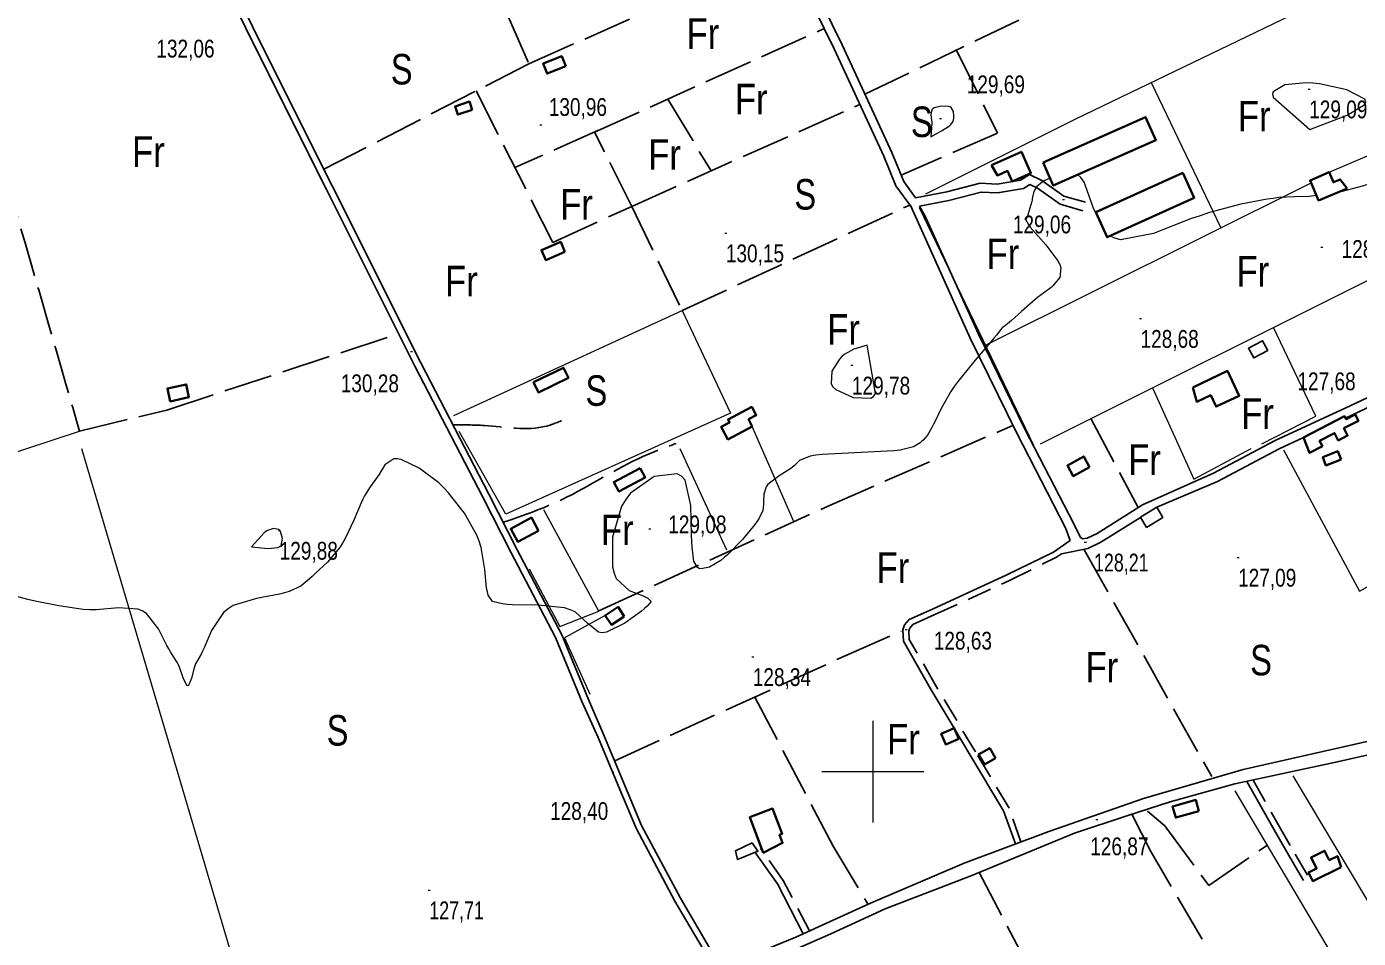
# Model space of a CAD drawing. Extents: x 483855 to 488461, y 4388206 to 4391419.
# Drawn here: x 485084 to 485739, y 4389918 to 4390366 of the extents above; entities that cross this region are included whole.
import ezdxf
from ezdxf.enums import TextEntityAlignment as Align

# ---------------------------------------------------------------- set-up
doc = ezdxf.new("R2010")
doc.units = 0
doc.header["$LTSCALE"] = 4
doc.linetypes.add('LONG_DASHED', pattern=[7.5, 6, -1.5])
doc.linetypes.add('MEDIUM_DASHED', pattern=[4.5, 3, -1.5])
for name, color, linetype, lineweight in [('1', 7, 'Continuous', 13), ('21', 7, 'Continuous', 25), ('25', 7, 'LONG_DASHED', 25), ('36', 7, 'Continuous', 25), ('38', 7, 'Continuous', 25), ('47', 7, 'Continuous', 35), ('48', 7, 'MEDIUM_DASHED', 25), ('51', 7, 'Continuous', 13), ('7', 7, 'Continuous', 13), ('9', 7, 'Continuous', 13)]:
    doc.layers.add(name, color=color, linetype=linetype, lineweight=lineweight)
doc.layers.add('31', color=7, linetype='Continuous')

msp = doc.modelspace()

# ---------------------------------------------------------------- linework, layer by layer
at = {"layer": '1'}
for p, q in [((485500, 4390025), (485500, 4389975)), ((485475, 4390000), (485525, 4390000))]:
    msp.add_line(p, q, dxfattribs=at)
at = {"layer": '21'}
for points in [[(485694.2, 4390207.05), (485687.38, 4390203.36), (485684.67, 4390208.16), (485691.64, 4390211.77)], [(485440.6, 4389964.94), (485432.51, 4389961.1), (485433.49, 4389956.75), (485443.46, 4389960.82)]]:
    msp.add_lwpolyline(points, close=True, dxfattribs=at)
at = {"layer": '25'}
for p, q in [((485496.08, 4390333.01), (485726.76, 4390444.04)), ((485330.9, 4390348.01), (485457.19, 4390403.79)), ((485399.21, 4390330.61), (485420.45, 4390295.3)), ((485381.43, 4390277.88), (485493.62, 4390327.96)), ((485365.13, 4390315.25), (485324.03, 4390296.93)), ((485607.22, 4390173.52), (485630.52, 4390129.84)), ((485603.77, 4390109.32), (485666.64, 4389997.56))]:
    msp.add_line(p, q, dxfattribs=at)
for points in [[(485296.72, 4390425.72), (485330.9, 4390348.01), (485230.08, 4390296.09)], [(485304.91, 4390334.63), (485342.67, 4390260.18), (485381.43, 4390277.88), (485363.21, 4390314.38), (485476.08, 4390365.27)], [(485541.16, 4390354.71), (485561.33, 4390313.8), (485513.89, 4390293.28)], [(485381.43, 4390277.88), (485406.27, 4390226.61), (485518.24, 4390278.5)], [(485109.98, 4390167.39), (485152.87, 4390177.73), (485266.82, 4390215.24)], [(485365.2, 4390079.11), (485478.44, 4390130.71), (485568.84, 4390170.2)], [(485373.09, 4390005.28), (485486.33, 4390056.88), (485513.91, 4390068.99)], [(485441.88, 4390037), (485480.45, 4389963.38), (485497.61, 4389934.98)], [(485711.3, 4389834.77), (485677.02, 4389891.66), (485636.7, 4389960.68), (485627.54, 4389978.68)], [(485635.1, 4389980.56), (485643.58, 4389973.3), (485665.15, 4389944), (485694.02, 4389963.84)], [(485552.15, 4389950.66), (485590.17, 4389878.09), (485637.03, 4389800.53), (485571.13, 4389763.3)]]:
    msp.add_lwpolyline(points, dxfattribs=at)
at = {"layer": '36'}
for points in [[(485426.84, 4389904.19), (485462.15, 4389918.62), (485498.91, 4389935.32), (485544.96, 4389955.04), (485586.5, 4389970.62), (485633.09, 4389986.79), (485682.11, 4390001.08), (485760.41, 4390018.66), (485786.52, 4390024.44), (485817.17, 4390031.06), (485845.6, 4390037.42), (485862.58, 4390041.06), (485894.13, 4390046.76), (485921.74, 4390051.34), (485939.46, 4390053.47)], [(485457.64, 4389910.81), (485479.31, 4389920.29), (485505.99, 4389932.49), (485547.82, 4389948.54), (485599.1, 4389969.7), (485624.96, 4389978.29), (485646.18, 4389985.15), (485678.05, 4389994.06), (485727.69, 4390004.64), (485758.06, 4390011.52)]]:
    msp.add_lwpolyline(points, dxfattribs=at)
at = {"layer": '38', "linetype": 'MEDIUM_DASHED'}
msp.add_line((485445.68, 4389960.95), (485444.8, 4389962.2), dxfattribs=at)
at = {"layer": '38'}
for points in [[(485115.19, 4390517.05), (485120.9, 4390509.39), (485153.94, 4390442.23), (485197.14, 4390354.46), (485231.39, 4390286.11), (485274.74, 4390199.39), (485308.3, 4390134.85), (485322.07, 4390107.8), (485344.04, 4390065.9), (485357.15, 4390034.19)], [(485421.55, 4390481.77), (485421.57, 4390476.82), (485451.45, 4390415.49), (485480.94, 4390355.34), (485505.34, 4390302.62), (485511.39, 4390287.91), (485519.02, 4390277.43)], [(485425.89, 4390482.84), (485425.92, 4390477.83), (485455.36, 4390417.4), (485484.87, 4390357.21), (485509.33, 4390304.37), (485515.21, 4390290.05), (485521.05, 4390282.03), (485536.34, 4390285.07), (485552.75, 4390289.3), (485561.08, 4390288.86), (485572.58, 4390290.77), (485576.97, 4390293.53), (485583.14, 4390290.64), (485593.96, 4390282.92), (485604.49, 4390279.94)], [(485189.92, 4390376.61), (485200.1, 4390355.93), (485234.34, 4390287.59), (485277.68, 4390200.89), (485311.23, 4390136.36), (485325, 4390109.31), (485347.03, 4390067.3), (485360.2, 4390035.45)], [(485522.96, 4390277.98), (485537.31, 4390280.83), (485553.19, 4390284.92), (485561.32, 4390284.49), (485574.16, 4390286.61), (485577.27, 4390288.58), (485580.93, 4390286.86), (485592.05, 4390278.94), (485603.3, 4390275.75)], [(485518.45, 4390278.22), (485521.75, 4390271.05), (485547.88, 4390213.12), (485570.73, 4390166.31), (485594.74, 4390119.84), (485597.01, 4390113.64)], [(485522.96, 4390277.98), (485525.78, 4390273.13), (485551.98, 4390215.04), (485574.78, 4390168.34), (485598.79, 4390121.87), (485602.05, 4390115.15), (485603.27, 4390114.39), (485605.43, 4390114.78), (485610.29, 4390117.06), (485632.55, 4390131.12), (485667.48, 4390146.71), (485697.83, 4390162.74), (485734.63, 4390179.83), (485772.19, 4390197.44), (485807.34, 4390217.08), (485839.38, 4390233.64)], [(485732.44, 4390173.82), (485736.54, 4390175.73), (485774.26, 4390193.41), (485809.49, 4390213.09), (485841.46, 4390229.62)], [(485639.67, 4390129.93), (485669.46, 4390142.64), (485699.84, 4390158.68), (485711.74, 4390164.21)], [(485592.75, 4390107.08), (485605.77, 4390109.73), (485612.05, 4390112.82), (485631.62, 4390124.96)], [(485540.02, 4390021.35), (485528.23, 4390041.03), (485515, 4390064.17), (485514.76, 4390069.77), (485515.65, 4390072.08), (485517.8, 4390074.76), (485529.33, 4390079.87), (485565.84, 4390096.66), (485588.78, 4390107.95), (485597.01, 4390113.64)], [(485425.44, 4389903.58), (485405.35, 4389937.79), (485386.33, 4389973.58), (485378.33, 4389992.42), (485367.78, 4390017.92), (485360.2, 4390035.45)], [(485422.41, 4389902.73), (485402.69, 4389936.3), (485383.58, 4389972.27), (485375.52, 4389991.24), (485364.98, 4390016.72), (485357.15, 4390034.19)], [(485570.09, 4389964.47), (485564.33, 4389980.77), (485547.94, 4390008.13), (485540.23, 4390021)], [(485683.95, 4389995.14), (485696.76, 4389972.56), (485705.11, 4389958.02), (485711.81, 4389946.55)], [(485465.82, 4389920.29), (485453.09, 4389944.78), (485442.11, 4389960.29)]]:
    msp.add_lwpolyline(points, dxfattribs=at)
at = {"layer": '38', "linetype": 'MEDIUM_DASHED'}
for points in [[(485572.78, 4389965.47), (485567.03, 4389982.06), (485550.49, 4390009.66), (485530.8, 4390042.54), (485517.94, 4390065.02), (485517.76, 4390069.28), (485518.26, 4390070.57), (485519.67, 4390072.33), (485530.55, 4390077.16), (485567.12, 4390093.97), (485590.3, 4390105.38), (485592.75, 4390107.08)], [(485686.96, 4389995.78), (485699.3, 4389974.01), (485707.64, 4389959.49), (485714.34, 4389948.03)], [(485468.73, 4389922.12), (485455.91, 4389946.51), (485446.19, 4389960.24)]]:
    msp.add_lwpolyline(points, dxfattribs=at)
at = {"layer": '38', "linetype": 'LONG_DASHED'}
for points in [[(485014.04, 4390465.16), (485018.06, 4390459.11), (485044.44, 4390383.92), (485062.76, 4390327.24), (485083.13, 4390259.98), (485109.98, 4390167.39)], [(485293.5, 4390170.47), (485309.07, 4390170.11), (485339.52, 4390169.86), (485349.04, 4390173.4)], [(485318.26, 4390122.56), (485347.23, 4390133.79), (485387.18, 4390155.01), (485403.22, 4390161.26)]]:
    msp.add_spline(points, degree=3, dxfattribs=at)
at = {"layer": '47'}
for points in [[(485348.98, 4390346.84), (485339.83, 4390343.17), (485337.88, 4390348.02), (485347.03, 4390351.69)], [(485302.96, 4390325.31), (485295.9, 4390322.97), (485294.56, 4390327.02), (485301.62, 4390329.36)], [(485583.71, 4390299.51), (485634.1, 4390321.72), (485639.12, 4390310.33), (485588.73, 4390288.12)], [(485558.35, 4390298.12), (485573.04, 4390304.74), (485577.76, 4390294.24), (485568.51, 4390290.1), (485566.19, 4390295.27), (485561.25, 4390293.07)], [(485609.63, 4390274.95), (485652.38, 4390294.31), (485657.92, 4390282.08), (485615.17, 4390262.72)], [(485733.3, 4390286.7), (485719.14, 4390280.75), (485714.98, 4390290.63), (485724.4, 4390294.62), (485726.47, 4390289.7), (485729.85, 4390291.14)], [(485348.61, 4390255.54), (485339.15, 4390251.47), (485337.05, 4390256.35), (485346.51, 4390260.42)], [(485333.19, 4390191.46), (485347.95, 4390198.54), (485350.36, 4390193.51), (485335.6, 4390186.43)], [(485657.33, 4390188.84), (485674.34, 4390196.96), (485680.13, 4390184.81), (485668.79, 4390179.41), (485666.13, 4390184.98), (485659.38, 4390181.76)], [(485154.52, 4390182.01), (485163.76, 4390184.02), (485162.38, 4390190.35), (485153.14, 4390188.34)], [(485440.72, 4390169.58), (485428.72, 4390163.33), (485425.48, 4390169.54), (485429.6, 4390171.7), (485428.84, 4390173.14), (485440.49, 4390179.31), (485442.65, 4390175.22), (485438.91, 4390173.25)], [(485711.83, 4390164.25), (485731.99, 4390174.7), (485732.69, 4390173.33), (485737.09, 4390175.59), (485738.72, 4390172.41), (485731.59, 4390168.77), (485733.43, 4390165.15), (485728.87, 4390162.83), (485727.03, 4390166.43), (485719.7, 4390162.68), (485721.07, 4390159.99), (485714.66, 4390156.72)], [(485606.61, 4390149.67), (485598.56, 4390145.22), (485595.65, 4390150.48), (485603.7, 4390154.93)], [(485730.22, 4390153.47), (485722.82, 4390150.51), (485721.22, 4390154.51), (485728.62, 4390157.47)], [(485385.61, 4390149.16), (485372.64, 4390142.33), (485375.06, 4390137.74), (485388.03, 4390144.57)], [(485335.63, 4390118.4), (485325.45, 4390112.91), (485321.98, 4390119.35), (485332.16, 4390124.84)], [(485377.78, 4390076.31), (485371.43, 4390072.17), (485368.4, 4390076.82), (485374.75, 4390080.96)], [(485542.31, 4390016.19), (485535.85, 4390013.4), (485533.61, 4390018.58), (485540.07, 4390021.37)], [(485560.33, 4390006.69), (485554.86, 4390003.5), (485552, 4390008.4), (485557.47, 4390011.59)], [(485660.29, 4389980.6), (485648.94, 4389977.4), (485647.39, 4389982.91), (485658.74, 4389986.11)], [(485446.01, 4389960.15), (485439.46, 4389977.61), (485450.74, 4389981.85), (485455.41, 4389969.4), (485454.18, 4389968.96), (485455.61, 4389964.94)], [(485730.25, 4389952.96), (485716.38, 4389946.11), (485714.23, 4389950.43), (485718.18, 4389952.4), (485715.47, 4389957.81), (485722.09, 4389961.13), (485724.41, 4389956.48), (485728.47, 4389958.52)]]:
    msp.add_lwpolyline(points, close=True, dxfattribs=at)
at = {"layer": '48'}
msp.add_lwpolyline([(485642.65, 4390124.84), (485634.56, 4390120.04), (485631.54, 4390125.13), (485639.63, 4390129.93)], close=True, dxfattribs=at)
at = {"layer": '51'}
for p, q in [((485636.87, 4390338.72), (485671.11, 4390267.33)), ((485724.4, 4390294.62), (485789.81, 4390322.73)), ((485555.45, 4390209.69), (485715.49, 4390289.45)), ((485579.21, 4390160.35), (485522.91, 4390277.21)), ((485813.74, 4390276.63), (485582.21, 4390161.03)), ((484853.27, 4390083.47), (485109.98, 4390167.39)), ((485460.97, 4390123.25), (485440.72, 4390169.58)), ((485405.18, 4390158.87), (485427.99, 4390108.95))]:
    msp.add_line(p, q, dxfattribs=at)
for points in [[(485750.16, 4390393.33), (485599.65, 4390320.77), (485525.9, 4390283.89)], [(485294.06, 4390175.11), (485406.27, 4390226.61), (485430.05, 4390176.16), (485319.56, 4390126.55), (485296.54, 4390167.17)], [(485691.2, 4390161.14), (485717.89, 4390174.68), (485696.99, 4390218.35)], [(485637.45, 4390188.62), (485657.85, 4390143.83), (485686.03, 4390158.8)], [(485110.97, 4390158.91), (485158.72, 4389997.48), (485206.92, 4389834.26)], [(485701.86, 4390158.23), (485739.25, 4390088.75), (485775.98, 4390109.21), (485752.24, 4390157.3)], [(485331.01, 4390099.63), (485346.13, 4390071.3), (485365.33, 4390078.84), (485338.31, 4390128.75)], [(485368.4, 4390076.82), (485348.39, 4390065.83), (485360.89, 4390038.02)], [(485706.55, 4389997.93), (485784.02, 4389868.13), (485757.19, 4389857.14), (485678.2, 4389990.53)]]:
    msp.add_lwpolyline(points, dxfattribs=at)
at = {"layer": '7'}
for p, q in [((485714.05, 4390335.51), (485715.05, 4390335.51)), ((485336.3, 4390318.01), (485337.3, 4390318.01)), ((485532.84, 4390321.11), (485533.84, 4390321.11)), ((485593.29, 4390281.3), (485594.29, 4390281.3)), ((485427.23, 4390264.75), (485428.23, 4390264.75)), ((485720.32, 4390257.8), (485721.32, 4390257.8)), ((485631.12, 4390222.7), (485632.12, 4390222.7)), ((485272.65, 4390206.51), (485273.65, 4390206.51)), ((485489.23, 4390199.74), (485490.23, 4390199.74)), ((485207.83, 4390118.56), (485208.83, 4390118.56)), ((485389.81, 4390119.39), (485390.81, 4390119.39)), ((485603.99, 4390112.76), (485604.99, 4390112.76)), ((485679.09, 4390105.31), (485680.09, 4390105.31)), ((485515.92, 4390069.93), (485516.92, 4390069.93)), ((485440.48, 4390056.46), (485441.48, 4390056.46)), ((485371.71, 4389999.86), (485372.71, 4389999.86)), ((485609.61, 4389976.47), (485610.61, 4389976.47)), ((485281.41, 4389941.8), (485282.41, 4389941.8))]:
    msp.add_line(p, q, dxfattribs=at)
at = {"layer": '9'}
msp.add_line((485610.51, 4390273.01), (485610.5, 4390273.02), dxfattribs=at)
for points in [[(485714.81, 4390315.57), (485733.17, 4390322.63), (485741.91, 4390327.9), (485742.33, 4390329.28), (485741.9, 4390330.61), (485733.14, 4390335.11), (485719.7, 4390338.08), (485716.31, 4390338.44), (485713.07, 4390338.61), (485702.59, 4390337.57), (485696.79, 4390334.24), (485696.51, 4390332.96), (485696.79, 4390331.53)], [(485528.45, 4390312.01), (485533.72, 4390314.99), (485537.13, 4390317.12), (485537.81, 4390317.64), (485538.39, 4390318.13), (485539.55, 4390319.64), (485539.84, 4390321.19), (485539.86, 4390321.7), (485539.87, 4390322.24), (485539.7, 4390324.5), (485538.58, 4390326.43), (485537.98, 4390326.76), (485537.26, 4390327), (485533.64, 4390327.15), (485530.18, 4390326.24), (485529.56, 4390325.83), (485529.08, 4390325.34), (485528.59, 4390322.95), (485528.91, 4390320.1), (485528.94, 4390319.31), (485528.96, 4390318.52)], [(485497.25, 4390209.67), (485490.71, 4390207.69), (485485.94, 4390205.08), (485484.74, 4390203.99), (485483.6, 4390202.74), (485479.91, 4390196.86), (485479.47, 4390190.65), (485480.38, 4390189.18), (485481.74, 4390187.83), (485490.35, 4390183.85), (485499.01, 4390183.52), (485500.4, 4390184.47), (485501.36, 4390185.87)], [(485194.45, 4390110.48), (485202.5, 4390109.74), (485207.46, 4390110.14), (485208.35, 4390110.59), (485209.04, 4390111.19), (485209.79, 4390114.6), (485208.74, 4390118.02), (485208.28, 4390118.63), (485207.75, 4390119.09), (485205.25, 4390119.52), (485202.33, 4390118.45), (485201.54, 4390117.97), (485200.75, 4390117.4)]]:
    msp.add_lwpolyline(points, close=True, dxfattribs=at)
for points in [[(485791, 4390306.33), (485780.87, 4390303.85), (485769.66, 4390301.74), (485766.84, 4390300.85), (485764.14, 4390299.84), (485755.42, 4390295.08), (485746.73, 4390290.14), (485744.05, 4390289), (485741.25, 4390287.97), (485730.16, 4390285.07), (485728.95, 4390284.87)], [(485587.11, 4390291.8), (485586.01, 4390291.31), (485584.55, 4390290.53), (485583.3, 4390289.79), (485580.51, 4390287.39), (485579.35, 4390285.43), (485579.13, 4390284.97), (485578.95, 4390284.53), (485578.64, 4390283.24), (485578.41, 4390281.63), (485578.27, 4390280.99), (485578.1, 4390280.27), (485577.23, 4390276.98), (485576.28, 4390273.76), (485576.06, 4390273.08), (485575.86, 4390272.5), (485575.29, 4390271.18), (485576.5, 4390268.88), (485577.43, 4390267.68), (485578.62, 4390266.23), (485585.03, 4390258.96), (485591, 4390251.11), (485591.92, 4390249.29), (485592.51, 4390247.63), (485591.96, 4390242.92), (485589.22, 4390239.56), (485588.43, 4390238.75), (485587.62, 4390238), (485584.62, 4390235.7), (485580.96, 4390233.06), (485579.75, 4390232.09), (485578.45, 4390231.01), (485573.06, 4390226.23), (485568.12, 4390221.76), (485567.12, 4390220.87), (485566.27, 4390220.13), (485564.5, 4390218.75), (485563.82, 4390218.29), (485563.65, 4390218.14), (485563.49, 4390217.99), (485563.01, 4390217.34), (485560.8, 4390214.61), (485559.55, 4390213.14), (485558.04, 4390211.35), (485550.28, 4390202.32), (485541.92, 4390191.94), (485540.02, 4390189.31), (485538.3, 4390186.79), (485533.62, 4390178.55), (485530.45, 4390171.94), (485529.69, 4390170.44), (485528.98, 4390169.09), (485526.85, 4390165.42), (485524.71, 4390162.87), (485524, 4390162.23), (485523.23, 4390161.61), (485520.04, 4390159.61), (485513.42, 4390158.07), (485510.5, 4390157.74), (485507.11, 4390157.45), (485490.93, 4390156.77), (485475.08, 4390155.95), (485471.9, 4390155.57), (485469.24, 4390155.13), (485463.97, 4390153), (485461.31, 4390150.28), (485460.28, 4390149.46), (485459.14, 4390148.62), (485453.97, 4390145.34), (485449.16, 4390141.87), (485448.24, 4390140.9), (485447.51, 4390139.93)], [(485610.5, 4390273.02), (485608.6, 4390276.46), (485603.85, 4390289.78), (485602.23, 4390292.03), (485600.74, 4390293.42)], [(485718.12, 4390283.16), (485716.87, 4390283.01), (485714.49, 4390282.77), (485707.33, 4390282.55), (485699.64, 4390282.15), (485696.91, 4390281.8), (485693.93, 4390281.35), (485681.01, 4390278.88), (485665.52, 4390274.77), (485660.92, 4390273.29), (485656.18, 4390271.66), (485637.96, 4390264.57), (485621.83, 4390261.48), (485618.42, 4390262.39), (485616.65, 4390263.39)], [(485447.51, 4390139.93), (485446.34, 4390136.39), (485446.28, 4390133), (485446.24, 4390132.12), (485446.19, 4390131.27), (485445.93, 4390128.39), (485444.18, 4390124.54), (485443.2, 4390123.07), (485441.99, 4390121.43), (485435.84, 4390114.05), (485428.76, 4390106.78), (485426.98, 4390105.22), (485425.27, 4390103.84), (485419.73, 4390100.46), (485415.48, 4390099.63), (485414.58, 4390099.86), (485413.79, 4390100.28), (485411.97, 4390103.47), (485411.11, 4390110.39), (485410.93, 4390113.17), (485410.79, 4390116.33), (485410.5, 4390130.83), (485407.68, 4390143.31), (485405.94, 4390145.19), (485403.78, 4390146.39), (485392.53, 4390145), (485380.89, 4390136.88), (485378.49, 4390133.82), (485376.45, 4390130.42), (485372.07, 4390115.24), (485372.07, 4390100.61), (485372.8, 4390097.55), (485373.84, 4390094.93), (485380.24, 4390089.06), (485387.04, 4390086.38), (485388.33, 4390085.76), (485389.38, 4390085.2), (485391.03, 4390083.64), (485389.04, 4390081.26), (485387.78, 4390080.19), (485386.21, 4390078.94), (485378, 4390072.91), (485369.02, 4390068.52), (485366.96, 4390068.29), (485365.09, 4390068.49), (485359.89, 4390072.78), (485353.72, 4390078.48), (485351.24, 4390079.56), (485348.43, 4390080.44), (485335.46, 4390081.81), (485322.79, 4390082.06), (485320.16, 4390082.23), (485317.92, 4390082.44), (485312.98, 4390083.55), (485310.91, 4390086.8), (485310.47, 4390088.36), (485310.1, 4390090.21), (485309.23, 4390099.3), (485307.41, 4390110.23), (485306.43, 4390113.25), (485305.25, 4390116.27), (485299.3, 4390127.13), (485291.43, 4390137.12), (485289.05, 4390139.58), (485286.58, 4390141.92), (485276.92, 4390149.25), (485268.09, 4390153.43), (485266.15, 4390153.77), (485264.42, 4390153.76), (485259.97, 4390150.78), (485257.03, 4390145.93), (485256.25, 4390144.73), (485255.49, 4390143.6), (485252.85, 4390140.05), (485250.07, 4390135.63), (485249.22, 4390133.95), (485248.34, 4390132.07), (485244.84, 4390123.62), (485240.57, 4390114.53), (485239.2, 4390112.25), (485237.75, 4390110.06), (485231.82, 4390103.01), (485225.87, 4390097.31), (485224.4, 4390095.97), (485223.01, 4390094.75), (485218.67, 4390091.2), (485213, 4390088.54), (485210.79, 4390087.87), (485208.29, 4390087.23), (485196.93, 4390085.15), (485185.51, 4390081.59), (485182.97, 4390080.01), (485180.7, 4390078.18), (485174.78, 4390069.43), (485171.23, 4390060.87), (485170.46, 4390059.15), (485169.78, 4390057.72), (485168.08, 4390054.9), (485166.94, 4390052.94), (485166.61, 4390052.05), (485166.27, 4390051)], [(485166.27, 4390051), (485164.99, 4390045.94), (485163.55, 4390042.27), (485163.11, 4390042.1), (485162.65, 4390042.3), (485160.83, 4390046.08), (485159.01, 4390051.32), (485158.55, 4390052.45), (485158.11, 4390053.43), (485156.65, 4390055.81), (485154.63, 4390058.89), (485153.83, 4390060.32), (485152.92, 4390062), (485148.8, 4390070.14), (485142.85, 4390077.67), (485140.8, 4390078.96), (485138.57, 4390079.9), (485129.06, 4390080.45), (485118.07, 4390079.56), (485114.91, 4390079.6), (485111.7, 4390079.77), (485099.68, 4390081.42), (485089, 4390083.63), (485086.64, 4390084.16), (485084.53, 4390084.65), (485079.05, 4390086.1)]]:
    msp.add_lwpolyline(points, dxfattribs=at)

# ---------------------------------------------------------------- texts
at = {"layer": '31'}
for s, width, p in [('Fr', 0.85, (485416.47, 4390355.28)), ('S', 0.8, (485268.35, 4390337.8)), ('Fr', 0.85, (485440.23, 4390323.12)), ('Fr', 0.85, (485687.56, 4390314.73)), ('S', 0.8, (485524.08, 4390311.94)), ('Fr', 0.85, (485143.82, 4390297.26)), ('Fr', 0.85, (485397.61, 4390295.86)), ('S', 0.8, (485466.78, 4390276.29)), ('Fr', 0.85, (485354.29, 4390271.4)), ('Fr', 0.85, (485563.99, 4390247.05)), ('Fr', 0.85, (485686.86, 4390238.47)), ('Fr', 0.85, (485297.7, 4390233.65)), ('Fr', 0.85, (485485.64, 4390209.88)), ('S', 0.8, (485364.08, 4390179.82)), ('Fr', 0.85, (485689.17, 4390168.5)), ('Fr', 0.85, (485633.58, 4390145.88)), ('Fr', 0.85, (485374.38, 4390111.32)), ('Fr', 0.85, (485509.92, 4390092.76)), ('S', 0.8, (485690.89, 4390047.32)), ('Fr', 0.85, (485612.62, 4390043.83)), ('S', 0.8, (485236.8, 4390012.8)), ('Fr', 0.85, (485515.04, 4390008.45))]:
    msp.add_text(s, height=15, dxfattribs=dict(at, width=width)).set_placement(p, align=Align.CENTER)
at = {"layer": '7'}
for s, width, p in [('132,06', 0.8, (485147.7, 4390351.04)), ('129,69', 0.8, (485546.17, 4390333.48)), ('130,96', 0.8, (485340.66, 4390322.33)), ('129,09', 0.8, (485714.55, 4390321.14)), ('129,06', 0.8, (485568.85, 4390264.6)), ('130,15', 0.8, (485427.73, 4390250.38)), ('128,52', 0.8, (485730.48, 4390252.53)), ('128,68', 0.8, (485631.62, 4390208.33)), ('130,28', 0.8, (485238.36, 4390186.51)), ('129,78', 0.8, (485489.73, 4390185.37)), ('127,68', 0.8, (485708.78, 4390187.48)), ('129,08', 0.8, (485399.41, 4390117.16)), ('129,88', 0.8, (485208.33, 4390104.19)), ('128,21', 0.75, (485608.76, 4390098.39)), ('127,09', 0.8, (485679.59, 4390090.94)), ('128,63', 0.8, (485529.96, 4390060)), ('128,34', 0.8, (485440.98, 4390042.09)), ('128,40', 0.8, (485341.29, 4389976.26)), ('126,87', 0.8, (485606.9, 4389958.89)), ('127,71', 0.75, (485281.91, 4389927.43))]:
    msp.add_text(s, height=8.75, dxfattribs=dict(at, width=width)).set_placement(p)

doc.saveas('drawing.dxf')
